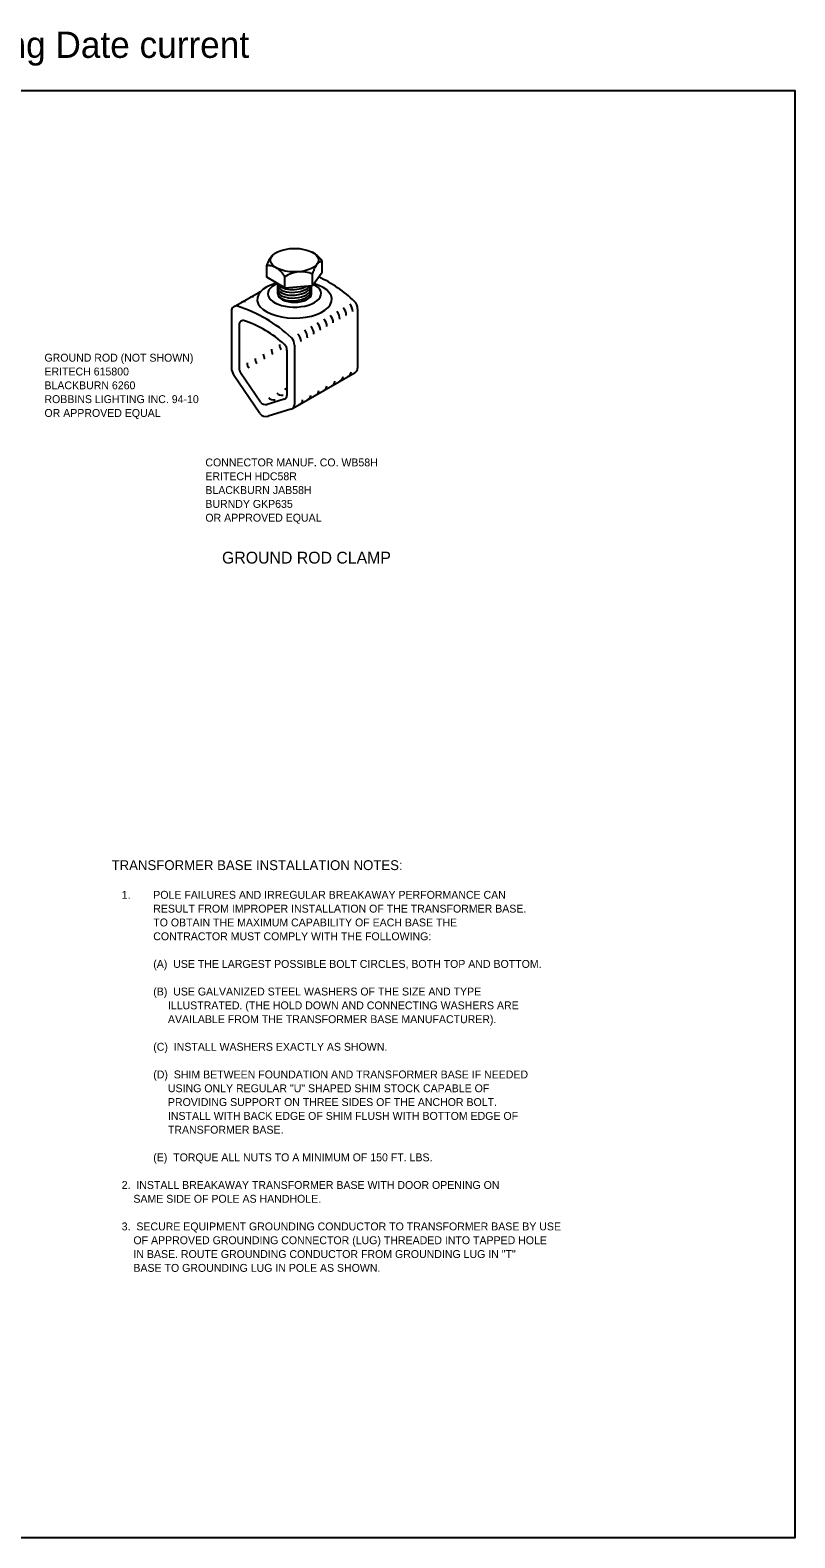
# Model space of a CAD drawing. Extents: x 99978 to 113378, y 99891 to 102182.
# Drawn here: x 102016 to 103178, y 99891 to 102182 of the extents above; entities that cross this region are included whole.
import ezdxf

# ---------------------------------------------------------------- set-up
doc = ezdxf.new("R2010")
doc.units = 0
for name, color, linetype in [('Border Line', 7, 'Continuous'), ('Border Organizer Shape', 7, 'Continuous'), ('Default', 7, 'Continuous')]:
    doc.layers.add(name, color=color, linetype=linetype)

msp = doc.modelspace()

# ---------------------------------------------------------------- linework, layer by layer
at = {"layer": 'Border Organizer Shape'}
for p, q in [((102375.7, 101806.7), (102375.7, 101823.7)), ((102459.5, 101814.1), (102459.5, 101831.1)), ((102403, 101790.4), (102375.7, 101806.7)), ((102385.6, 101796.4), (102389.4, 101798.5)), ((102392.1, 101781.5), (102392.1, 101796)), ((102403, 101790.4), (102403, 101807.4)), ((102403, 101790.4), (102445, 101794.1)), ((102443.2, 101781.5), (102443.2, 101793.5)), ((102445, 101794.1), (102459.5, 101814.1)), ((102445, 101794.1), (102445, 101811.1)), ((102326.7, 101762.4), (102366.7, 101785.5)), ((102321.8, 101755.2), (102321.8, 101668.6)), ((102513.5, 101758.6), (102513.5, 101668.6)), ((102333.3, 101734.9), (102333.3, 101669.2)), ((102417.6, 101703.2), (102417.6, 101613.3)), ((102406.1, 101695.5), (102406.1, 101627.1)), ((102364.9, 101599.7), (102325, 101658.3)), ((102366.1, 101616.8), (102335.7, 101661.3)), ((102414.7, 101607.2), (102509.6, 101662)), ((102402, 101621.5), (102375.9, 101613.4)), ((102412.2, 101605.9), (102377.8, 101595.2))]:
    msp.add_line(p, q, dxfattribs=at)
for centre, radius, start, end in [((102427.2, 101773.2), 41.8, 64.8272, 125.2468), ((102391, 101790.6), 7.7, 98.2936, 121.6234), ((102360, 101610.2), 218.4, 47.008, 64.3625), ((102341.8, 101762.2), 7.7, 80.4945, 121.6234), ((102354.1, 101769.3), 7.7, 80.4945, 121.6234), ((102366.4, 101776.4), 7.7, 97.2362, 121.6234), ((102497.6, 101758.7), 15.9, 359.499, 44.7885), ((102329.5, 101755.2), 7.7, 80.4945, 180), ((102264.1, 101554.8), 218.4, 47.008, 72.2188), ((102460.7, 101737.4), 15.9, 359.499, 44.7885), ((102470.5, 101743.1), 15.9, 359.499, 44.7885), ((102480.4, 101748.8), 15.9, 359.499, 44.7885), ((102490.2, 101754.5), 15.9, 359.499, 44.7885), ((102339.1, 101734.9), 5.85, 80.4945, 180), ((102289.4, 101582.7), 166, 47.008, 72.2188), ((102421.4, 101714.7), 15.9, 359.499, 44.7885), ((102431.2, 101720.4), 15.9, 359.499, 44.7885), ((102441, 101726.1), 15.9, 359.499, 44.7885), ((102450.9, 101731.8), 15.9, 359.499, 44.7885), ((102408.7, 101704.6), 14, 180, 214.3031), ((102394, 101695.6), 12.1, 359.499, 44.7885), ((102401.7, 101703.4), 15.9, 359.499, 44.7885), ((102411.6, 101709.1), 15.9, 359.499, 44.7885), ((102371.8, 101683.3), 14, 180, 214.3031), ((102384.1, 101690.4), 14, 180, 214.3031), ((102396.4, 101697.5), 14, 180, 214.3031), ((102340.2, 101668.6), 18.4, 180, 214.3031), ((102347.3, 101669.2), 14, 180, 214.3031), ((102359.6, 101676.3), 14, 180, 214.3031), ((102483.7, 101655.9), 7.71, 287.2672, 0), ((102496, 101663), 7.71, 287.2672, 0), ((102505.8, 101668.7), 7.71, 299.5254, 359.2675), ((102410.2, 101643), 8.75, 214.3049, 242.5558), ((102446.8, 101634.6), 7.71, 287.2672, 0), ((102459.1, 101641.7), 7.71, 287.2672, 0), ((102471.4, 101648.8), 7.71, 287.2672, 0), ((102373.3, 101621.7), 8.75, 214.3049, 287.2605), ((102385.6, 101628.8), 8.75, 214.3049, 287.2605), ((102397.9, 101635.9), 8.75, 214.3049, 287.2605), ((102400.3, 101627.1), 5.86, 287.2672, 0), ((102409.9, 101613.3), 7.71, 287.2672, 0), ((102422.2, 101620.4), 7.71, 287.2672, 0), ((102434.5, 101627.5), 7.71, 287.2672, 0), ((102374.4, 101606.2), 11.5, 214.3049, 287.2605)]:
    msp.add_arc(centre, radius, start, end, dxfattribs=at)
msp.add_ellipse((102417.6, 101832.5), major_axis=(36.5, 0), ratio=0.490099, dxfattribs=at)
for centre, major_axis, start_param, end_param in [((102417.6, 101772.9), (56.7, 0), 2.069881, 7.305427), ((102417.6, 101781.5), (40.5, 0), 2.252674, 7.070209), ((102417.5, 101792.2), (25.5, 2.2), 3.141593, 6.283185), ((102417.5, 101796.5), (25.5, 2.2), 3.141593, 5.899972), ((102417.5, 101800.7), (25.5, 2.2), 3.288097, 5.499544), ((102417.5, 101787.9), (25.5, 2.2), 3.141593, 6.283185), ((102417.5, 101783.7), (25.5, 2.2), 3.141593, 6.283185), ((102417.6, 101781.5), (25.6, 0), 3.141593, 6.283185)]:
    msp.add_ellipse(centre, major_axis=major_axis, ratio=0.5, start_param=start_param, end_param=end_param, dxfattribs=at)
for points in [[(102375.7, 101823.7), (102378, 101830.5), (102379.8, 101834.3), (102381, 101836.3), (102383, 101839.1), (102384.6, 101840.6), (102386, 101841.8), (102388.4, 101843.3)], [(102459.5, 101831.1), (102457.9, 101833.5), (102451.9, 101839.5), (102450.6, 101840.8), (102448.7, 101842.3), (102444.5, 101844.7)], [(102403, 101807.4), (102400, 101811.8), (102397.2, 101815), (102394, 101818.1), (102391.1, 101820.1), (102388.2, 101821.7), (102383.9, 101823.3), (102380.2, 101824.1), (102377.5, 101824.2), (102375.7, 101823.7)], [(102445, 101811.1), (102447.3, 101817.9), (102449, 101821.7), (102450.9, 101824.8), (102452.4, 101826.9), (102454.6, 101829.1), (102456.9, 101830.6), (102458.6, 101831.1), (102459.5, 101831.1)]]:
    msp.add_spline(points, degree=3, dxfattribs=at)
at = {"layer": 'Default'}
msp.add_lwpolyline([(99978.4, 102090.2), (103178.1, 102090.2), (103178.1, 99890.6), (99978.4, 99890.6)], close=True, dxfattribs=at)

# ---------------------------------------------------------------- texts
at = {"layer": 'Border Line'}
msp.add_text('Effective Letting Date current', height=40, dxfattribs=at).set_placement((101658.8, 102140))
at = {"layer": 'Border Organizer Shape'}
for s, height, p in [('GROUND ROD (NOT SHOWN)', 12, (102037.5, 101678.3)), ('ERITECH 615800', 12, (102037.5, 101657.3)), ('BLACKBURN 6260', 12, (102037.5, 101636.3)), ('ROBBINS LIGHTING INC. 94-10 ', 12, (102037.5, 101615.3)), ('OR APPROVED EQUAL', 12, (102037.5, 101594.3)), ('CONNECTOR MANUF. CO. WB58H', 12, (102282.1, 101519.1)), ('ERITECH HDC58R', 12, (102282.1, 101498.1)), ('BLACKBURN JAB58H', 12, (102282.1, 101477.1)), ('BURNDY GKP635', 12, (102282.1, 101456.1)), ('OR APPROVED EQUAL', 12, (102282.1, 101435.1)), ('GROUND ROD CLAMP', 18, (102307.4, 101371.4)), ('TRANSFORMER BASE INSTALLATION NOTES:', 15, (102139.5, 100905.5)), ('1.', 12, (102154.9, 100861.9)), ('POLE FAILURES AND IRREGULAR BREAKAWAY PERFORMANCE CAN', 12, (102202.9, 100861.9)), ('RESULT FROM IMPROPER INSTALLATION OF THE TRANSFORMER BASE.', 12, (102202.9, 100840.9)), ('TO OBTAIN THE MAXIMUM CAPABILITY OF EACH BASE THE', 12, (102202.9, 100819.9)), ('CONTRACTOR MUST COMPLY WITH THE FOLLOWING:', 12, (102202.9, 100798.9)), ('(A)  USE THE LARGEST POSSIBLE BOLT CIRCLES, BOTH TOP AND BOTTOM.', 12, (102202.9, 100756.9)), ('(B)  USE GALVANIZED STEEL WASHERS OF THE SIZE AND TYPE', 12, (102202.9, 100714.9)), ('     ILLUSTRATED. (THE HOLD DOWN AND CONNECTING WASHERS ARE', 12, (102202.9, 100693.9)), ('     AVAILABLE FROM THE TRANSFORMER BASE MANUFACTURER).', 12, (102202.9, 100672.9)), ('(C)  INSTALL WASHERS EXACTLY AS SHOWN.', 12, (102202.9, 100630.9)), ('(D)  SHIM BETWEEN FOUNDATION AND TRANSFORMER BASE IF NEEDED', 12, (102202.9, 100588.9)), ('     USING ONLY REGULAR "U" SHAPED SHIM STOCK CAPABLE OF', 12, (102202.9, 100567.9)), ('     PROVIDING SUPPORT ON THREE SIDES OF THE ANCHOR BOLT.', 12, (102202.9, 100546.9)), ('     INSTALL WITH BACK EDGE OF SHIM FLUSH WITH BOTTOM EDGE OF', 12, (102202.9, 100525.9)), ('     TRANSFORMER BASE.', 12, (102202.9, 100504.9)), ('(E)  TORQUE ALL NUTS TO A MINIMUM OF 150 FT. LBS.', 12, (102202.9, 100462.9)), ('2.  INSTALL BREAKAWAY TRANSFORMER BASE WITH DOOR OPENING ON', 12, (102154.9, 100420.9)), ('    SAME SIDE OF POLE AS HANDHOLE.', 12, (102154.9, 100399.9)), ('3.  SECURE EQUIPMENT GROUNDING CONDUCTOR TO TRANSFORMER BASE BY USE', 12, (102154.9, 100357.9)), ('    OF APPROVED GROUNDING CONNECTOR (LUG) THREADED INTO TAPPED HOLE', 12, (102154.9, 100336.9)), ('    IN BASE. ROUTE GROUNDING CONDUCTOR FROM GROUNDING LUG IN "T"', 12, (102154.9, 100315.9)), ('    BASE TO GROUNDING LUG IN POLE AS SHOWN.', 12, (102154.9, 100294.9))]:
    msp.add_text(s, height=height, dxfattribs=at).set_placement(p)

doc.saveas('drawing.dxf')
